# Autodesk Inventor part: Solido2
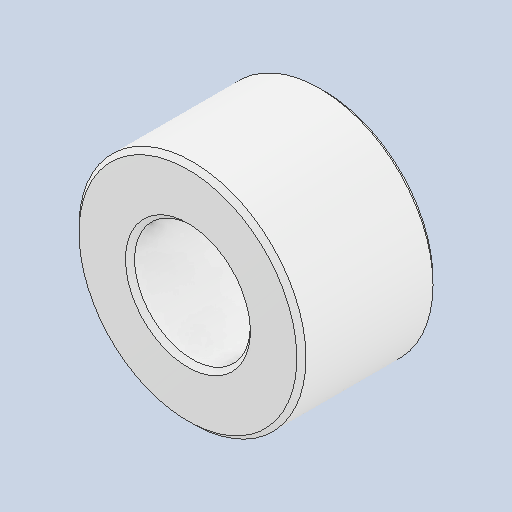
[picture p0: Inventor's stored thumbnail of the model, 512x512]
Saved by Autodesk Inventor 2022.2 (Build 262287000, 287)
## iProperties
Created: 2024-10
Part Number: Solido2
Material: Generico
Document SubType Name: Modeling
Designer: 18907419
Density: 1 g/cm^3
Appearance: Default
Author: 18907419
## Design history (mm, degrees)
feature "Solido2"
node "Solido1"
